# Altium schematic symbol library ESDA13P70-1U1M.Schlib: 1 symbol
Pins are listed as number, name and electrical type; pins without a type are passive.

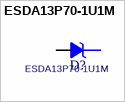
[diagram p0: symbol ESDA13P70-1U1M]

## ESDA13P70-1U1M
designator D?
pins: 1 K, 2 A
